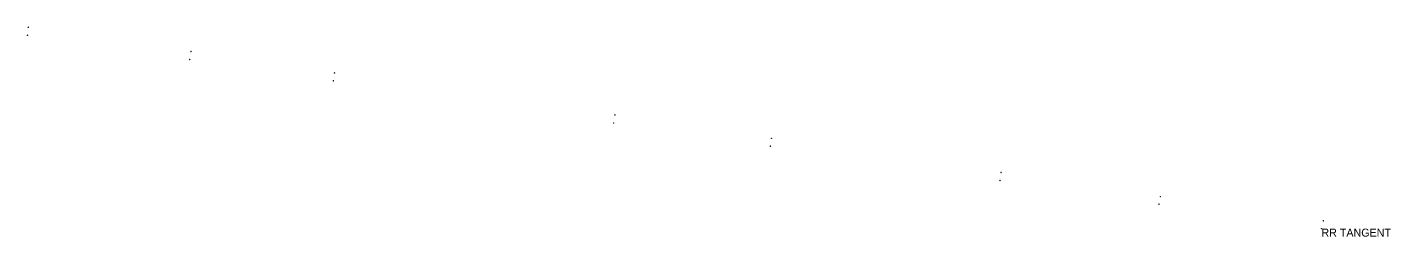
# Model space of a CAD drawing. Extents: x 878399 to 889864, y 1564003 to 1567413.
# Drawn here: x 881732 to 882583, y 1565411 to 1565542 of the extents above; entities that cross this region are included whole.
import ezdxf

# ---------------------------------------------------------------- set-up
doc = ezdxf.new("R2010")
doc.units = 0
doc.layers.add('S_MSC_PT_SYM', color=7, linetype='Continuous')
doc.layers.add('S_RAILROAD_ANNOT', color=7, linetype='Continuous')

msp = doc.modelspace()

# ---------------------------------------------------------------- linework, layer by layer
at = {"layer": 'S_MSC_PT_SYM'}
for points in [[(881731.56, 1565536.76), (881731.56, 1565536.81), (881731.56, 1565536.76), (881731.51, 1565536.76), (881731.56, 1565536.76), (881731.56, 1565536.71), (881731.56, 1565536.76), (881731.61, 1565536.76)], [(881732.17, 1565541.75), (881732.17, 1565541.8), (881732.17, 1565541.75), (881732.12, 1565541.75), (881732.17, 1565541.75), (881732.17, 1565541.7), (881732.17, 1565541.75), (881732.22, 1565541.75)], [(881833.89, 1565526.62), (881833.89, 1565526.67), (881833.89, 1565526.62), (881833.84, 1565526.62), (881833.89, 1565526.62), (881833.89, 1565526.57), (881833.89, 1565526.62), (881833.94, 1565526.62)], [(881833.02, 1565521.73), (881833.02, 1565521.78), (881833.02, 1565521.73), (881832.97, 1565521.73), (881833.02, 1565521.73), (881833.02, 1565521.68), (881833.02, 1565521.73), (881833.07, 1565521.73)], [(881923.36, 1565513.24), (881923.36, 1565513.29), (881923.36, 1565513.24), (881923.31, 1565513.24), (881923.36, 1565513.24), (881923.36, 1565513.19), (881923.36, 1565513.24), (881923.41, 1565513.24)], [(881922.82, 1565508.26), (881922.82, 1565508.31), (881922.82, 1565508.26), (881922.77, 1565508.26), (881922.82, 1565508.26), (881922.82, 1565508.21), (881922.82, 1565508.26), (881922.87, 1565508.26)], [(882098.67, 1565486.95), (882098.67, 1565487), (882098.67, 1565486.95), (882098.62, 1565486.95), (882098.67, 1565486.95), (882098.67, 1565486.9), (882098.67, 1565486.95), (882098.72, 1565486.95)], [(882097.96, 1565481.98), (882097.96, 1565482.03), (882097.96, 1565481.98), (882097.91, 1565481.98), (882097.96, 1565481.98), (882097.96, 1565481.93), (882097.96, 1565481.98), (882098.01, 1565481.98)], [(882195.79, 1565467.41), (882195.79, 1565467.46), (882195.79, 1565467.41), (882195.74, 1565467.41), (882195.79, 1565467.41), (882195.79, 1565467.36), (882195.79, 1565467.41), (882195.84, 1565467.41)], [(882196.46, 1565472.38), (882196.46, 1565472.43), (882196.46, 1565472.38), (882196.41, 1565472.38), (882196.46, 1565472.38), (882196.46, 1565472.33), (882196.46, 1565472.38), (882196.51, 1565472.38)], [(882339.88, 1565450.88), (882339.88, 1565450.93), (882339.88, 1565450.88), (882339.83, 1565450.88), (882339.88, 1565450.88), (882339.88, 1565450.83), (882339.88, 1565450.88), (882339.93, 1565450.88)], [(882339.22, 1565445.98), (882339.22, 1565446.03), (882339.22, 1565445.98), (882339.17, 1565445.98), (882339.22, 1565445.98), (882339.22, 1565445.93), (882339.22, 1565445.98), (882339.27, 1565445.98)], [(882439.49, 1565435.92), (882439.49, 1565435.97), (882439.49, 1565435.92), (882439.44, 1565435.92), (882439.49, 1565435.92), (882439.49, 1565435.87), (882439.49, 1565435.92), (882439.54, 1565435.92)], [(882438.62, 1565431.13), (882438.62, 1565431.18), (882438.62, 1565431.13), (882438.57, 1565431.13), (882438.62, 1565431.13), (882438.62, 1565431.08), (882438.62, 1565431.13), (882438.67, 1565431.13)], [(882540.07, 1565415.88), (882540.07, 1565415.93), (882540.07, 1565415.88), (882540.02, 1565415.88), (882540.07, 1565415.88), (882540.07, 1565415.83), (882540.07, 1565415.88), (882540.12, 1565415.88)], [(882541.23, 1565420.71), (882541.23, 1565420.76), (882541.23, 1565420.71), (882541.18, 1565420.71), (882541.23, 1565420.71), (882541.23, 1565420.66), (882541.23, 1565420.71), (882541.28, 1565420.71)]]:
    msp.add_lwpolyline(points, dxfattribs=at)

# ---------------------------------------------------------------- texts
at = {"layer": 'S_RAILROAD_ANNOT'}
msp.add_text('RR TANGENT', height=5, dxfattribs=at).set_placement((882540.07, 1565410.88))

doc.saveas('drawing.dxf')
